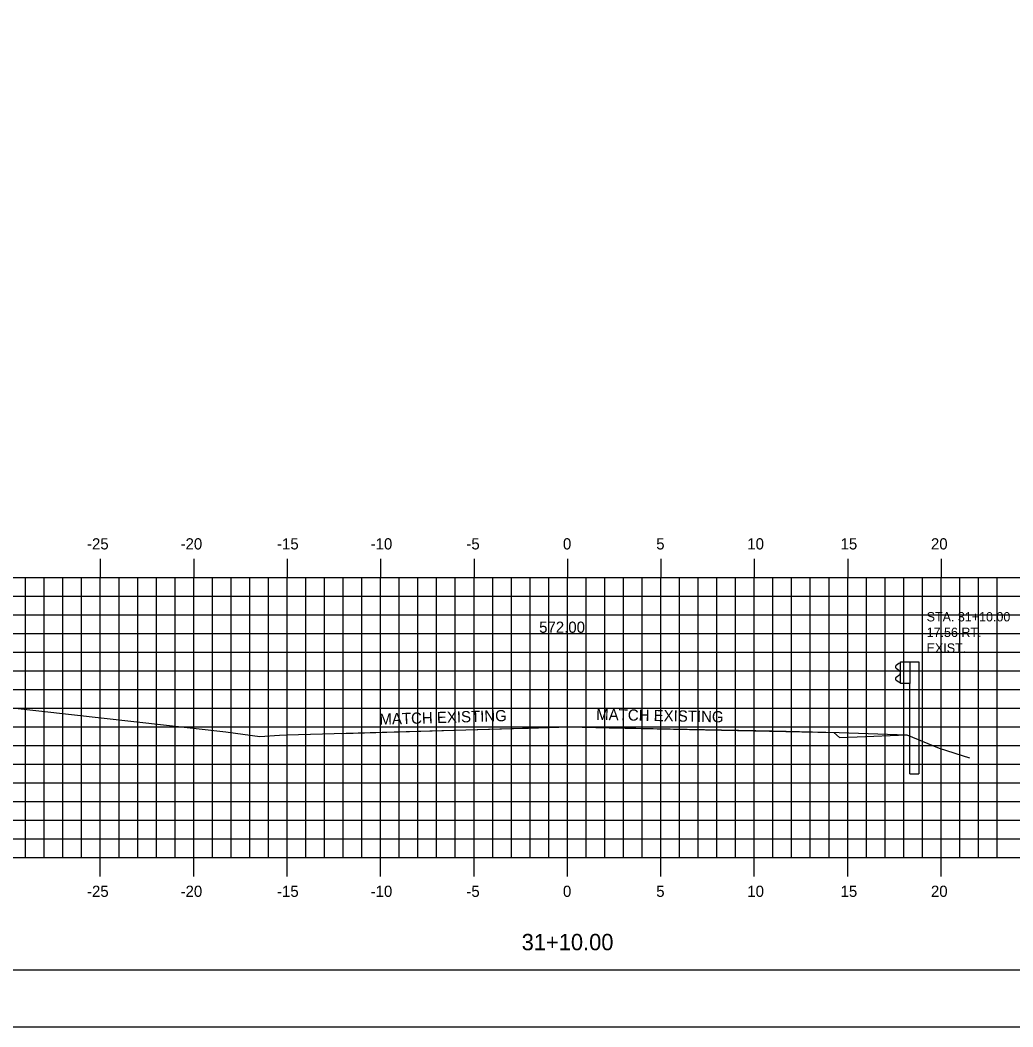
# Model space of a CAD drawing. Extents: x 1048552 to 1048722, y 781630 to 781740.
# Drawn here: x 1048606 to 1048659.1, y 781630.1 to 781684 of the extents above; entities that cross this region are included whole.
import ezdxf

# ---------------------------------------------------------------- set-up
doc = ezdxf.new("R2010")
doc.units = 0
for name, color, linetype in [('ANNOTATION', 7, 'Continuous'), ('D_Roadway_Centerline', 7, 'Continuous'), ('D_Roadway_Centerline_Text', 7, 'Continuous'), ('D_Text_Monospaced', 7, 'Continuous'), ('Default', 7, 'Continuous'), ('H_V ANNOTATION', 7, 'Continuous'), ('M_Guardrail', 7, 'Continuous'), ('MAJOR', 7, 'Continuous'), ('MINOR', 7, 'Continuous'), ('S_Guardrail_Beam', 7, 'Continuous'), ('S_Roadway_Centerline', 7, 'Continuous'), ('S_Roadway_Edge_Pavement', 7, 'Continuous')]:
    doc.layers.add(name, color=color, linetype=linetype)

msp = doc.modelspace()

# ---------------------------------------------------------------- linework, layer by layer
at = {"layer": 'D_Roadway_Centerline'}
msp.add_lwpolyline([(1048623.166, 781645.848), (1048635.246, 781646.2), (1048646.246, 781645.98), (1048649.796, 781645.893), (1048653.408, 781645.769)], dxfattribs=at)
at = {"layer": 'Default'}
msp.add_line((1048560.247, 781633.195), (1048720.247, 781633.195), dxfattribs=at)
msp.add_lwpolyline([(1048552.153, 781630.136), (1048722.153, 781630.136), (1048722.153, 781740.136), (1048552.153, 781740.136)], close=True, dxfattribs=at)
at = {"layer": 'M_Guardrail'}
for p, q in [((1048653.565, 781649.677), (1048654.057, 781649.677)), ((1048654.057, 781649.677), (1048654.057, 781643.677)), ((1048653.565, 781643.677), (1048653.565, 781648.511)), ((1048653.565, 781643.677), (1048654.057, 781643.677))]:
    msp.add_line(p, q, dxfattribs=at)
at = {"layer": 'MAJOR'}
for p, q in [((1048610.246, 781655.197), (1048610.246, 781654.195)), ((1048610.246, 781655.197), (1048610.246, 781654.195)), ((1048615.246, 781655.197), (1048615.246, 781654.195)), ((1048615.246, 781655.197), (1048615.246, 781654.195)), ((1048620.246, 781655.197), (1048620.246, 781654.195)), ((1048620.246, 781655.197), (1048620.246, 781654.195)), ((1048625.246, 781655.197), (1048625.246, 781654.195)), ((1048625.246, 781655.197), (1048625.246, 781654.195)), ((1048630.246, 781655.197), (1048630.246, 781654.195)), ((1048630.246, 781655.197), (1048630.246, 781654.195)), ((1048635.246, 781655.197), (1048635.246, 781654.195)), ((1048635.246, 781655.197), (1048635.246, 781654.195)), ((1048640.246, 781655.197), (1048640.246, 781654.195)), ((1048640.246, 781655.197), (1048640.246, 781654.195)), ((1048645.246, 781655.197), (1048645.246, 781654.195)), ((1048645.246, 781655.197), (1048645.246, 781654.195)), ((1048650.246, 781655.197), (1048650.246, 781654.195)), ((1048650.246, 781655.197), (1048650.246, 781654.195)), ((1048655.246, 781655.197), (1048655.246, 781654.195)), ((1048655.246, 781655.197), (1048655.246, 781654.195)), ((1048565.246, 781654.195), (1048705.246, 781654.195)), ((1048565.246, 781654.195), (1048705.246, 781654.195)), ((1048565.246, 781654.195), (1048705.246, 781654.195)), ((1048565.246, 781654.195), (1048705.246, 781654.195)), ((1048610.246, 781639.195), (1048610.246, 781654.195)), ((1048610.246, 781639.195), (1048610.246, 781654.195)), ((1048615.246, 781639.195), (1048615.246, 781654.195)), ((1048615.246, 781639.195), (1048615.246, 781654.195)), ((1048620.246, 781639.195), (1048620.246, 781654.195)), ((1048620.246, 781639.195), (1048620.246, 781654.195)), ((1048625.246, 781639.195), (1048625.246, 781654.195)), ((1048625.246, 781639.195), (1048625.246, 781654.195)), ((1048630.246, 781639.195), (1048630.246, 781654.195)), ((1048630.246, 781639.195), (1048630.246, 781654.195)), ((1048635.246, 781639.195), (1048635.246, 781654.195)), ((1048635.246, 781639.195), (1048635.246, 781654.195)), ((1048640.246, 781639.195), (1048640.246, 781654.195)), ((1048640.246, 781639.195), (1048640.246, 781654.195)), ((1048645.246, 781639.195), (1048645.246, 781654.195)), ((1048645.246, 781639.195), (1048645.246, 781654.195)), ((1048650.246, 781639.195), (1048650.246, 781654.195)), ((1048650.246, 781639.195), (1048650.246, 781654.195)), ((1048655.246, 781639.195), (1048655.246, 781654.195)), ((1048655.246, 781639.195), (1048655.246, 781654.195)), ((1048565.246, 781649.195), (1048705.246, 781649.195)), ((1048565.246, 781649.195), (1048705.246, 781649.195)), ((1048565.246, 781644.195), (1048705.246, 781644.195)), ((1048565.246, 781644.195), (1048705.246, 781644.195)), ((1048565.246, 781639.195), (1048705.246, 781639.195)), ((1048565.246, 781639.195), (1048705.246, 781639.195)), ((1048565.246, 781639.195), (1048705.246, 781639.195)), ((1048565.246, 781639.195), (1048705.246, 781639.195)), ((1048610.246, 781638.193), (1048610.246, 781639.195)), ((1048610.246, 781638.193), (1048610.246, 781639.195)), ((1048615.246, 781638.193), (1048615.246, 781639.195)), ((1048615.246, 781638.193), (1048615.246, 781639.195)), ((1048620.246, 781638.193), (1048620.246, 781639.195)), ((1048620.246, 781638.193), (1048620.246, 781639.195)), ((1048625.246, 781638.193), (1048625.246, 781639.195)), ((1048625.246, 781638.193), (1048625.246, 781639.195)), ((1048630.246, 781638.193), (1048630.246, 781639.195)), ((1048630.246, 781638.193), (1048630.246, 781639.195)), ((1048635.246, 781638.193), (1048635.246, 781639.195)), ((1048635.246, 781638.193), (1048635.246, 781639.195)), ((1048640.246, 781638.193), (1048640.246, 781639.195)), ((1048640.246, 781638.193), (1048640.246, 781639.195)), ((1048645.246, 781638.193), (1048645.246, 781639.195)), ((1048645.246, 781638.193), (1048645.246, 781639.195)), ((1048650.246, 781638.193), (1048650.246, 781639.195)), ((1048650.246, 781638.193), (1048650.246, 781639.195)), ((1048655.246, 781638.193), (1048655.246, 781639.195)), ((1048655.246, 781638.193), (1048655.246, 781639.195))]:
    msp.add_line(p, q, dxfattribs=at)
at = {"layer": 'MINOR'}
for p, q in [((1048606.246, 781639.195), (1048606.246, 781654.195)), ((1048606.246, 781639.195), (1048606.246, 781654.195)), ((1048607.246, 781639.195), (1048607.246, 781654.195)), ((1048607.246, 781639.195), (1048607.246, 781654.195)), ((1048608.246, 781639.195), (1048608.246, 781654.195)), ((1048608.246, 781639.195), (1048608.246, 781654.195)), ((1048609.246, 781639.195), (1048609.246, 781654.195)), ((1048609.246, 781639.195), (1048609.246, 781654.195)), ((1048611.246, 781639.195), (1048611.246, 781654.195)), ((1048611.246, 781639.195), (1048611.246, 781654.195)), ((1048612.246, 781639.195), (1048612.246, 781654.195)), ((1048612.246, 781639.195), (1048612.246, 781654.195)), ((1048613.246, 781639.195), (1048613.246, 781654.195)), ((1048613.246, 781639.195), (1048613.246, 781654.195)), ((1048614.246, 781639.195), (1048614.246, 781654.195)), ((1048614.246, 781639.195), (1048614.246, 781654.195)), ((1048616.246, 781639.195), (1048616.246, 781654.195)), ((1048616.246, 781639.195), (1048616.246, 781654.195)), ((1048617.246, 781639.195), (1048617.246, 781654.195)), ((1048617.246, 781639.195), (1048617.246, 781654.195)), ((1048618.246, 781639.195), (1048618.246, 781654.195)), ((1048618.246, 781639.195), (1048618.246, 781654.195)), ((1048619.246, 781639.195), (1048619.246, 781654.195)), ((1048619.246, 781639.195), (1048619.246, 781654.195)), ((1048621.246, 781639.195), (1048621.246, 781654.195)), ((1048621.246, 781639.195), (1048621.246, 781654.195)), ((1048622.246, 781639.195), (1048622.246, 781654.195)), ((1048622.246, 781639.195), (1048622.246, 781654.195)), ((1048623.246, 781639.195), (1048623.246, 781654.195)), ((1048623.246, 781639.195), (1048623.246, 781654.195)), ((1048624.246, 781639.195), (1048624.246, 781654.195)), ((1048624.246, 781639.195), (1048624.246, 781654.195)), ((1048626.246, 781639.195), (1048626.246, 781654.195)), ((1048626.246, 781639.195), (1048626.246, 781654.195)), ((1048627.246, 781639.195), (1048627.246, 781654.195)), ((1048627.246, 781639.195), (1048627.246, 781654.195)), ((1048628.246, 781639.195), (1048628.246, 781654.195)), ((1048628.246, 781639.195), (1048628.246, 781654.195)), ((1048629.246, 781639.195), (1048629.246, 781654.195)), ((1048629.246, 781639.195), (1048629.246, 781654.195)), ((1048631.246, 781639.195), (1048631.246, 781654.195)), ((1048631.246, 781639.195), (1048631.246, 781654.195)), ((1048632.246, 781639.195), (1048632.246, 781654.195)), ((1048632.246, 781639.195), (1048632.246, 781654.195)), ((1048633.246, 781639.195), (1048633.246, 781654.195)), ((1048633.246, 781639.195), (1048633.246, 781654.195)), ((1048634.246, 781639.195), (1048634.246, 781654.195)), ((1048634.246, 781639.195), (1048634.246, 781654.195)), ((1048636.246, 781639.195), (1048636.246, 781654.195)), ((1048636.246, 781639.195), (1048636.246, 781654.195)), ((1048637.246, 781639.195), (1048637.246, 781654.195)), ((1048637.246, 781639.195), (1048637.246, 781654.195)), ((1048638.246, 781639.195), (1048638.246, 781654.195)), ((1048638.246, 781639.195), (1048638.246, 781654.195)), ((1048639.246, 781639.195), (1048639.246, 781654.195)), ((1048639.246, 781639.195), (1048639.246, 781654.195)), ((1048641.246, 781639.195), (1048641.246, 781654.195)), ((1048641.246, 781639.195), (1048641.246, 781654.195)), ((1048642.246, 781639.195), (1048642.246, 781654.195)), ((1048642.246, 781639.195), (1048642.246, 781654.195)), ((1048643.246, 781639.195), (1048643.246, 781654.195)), ((1048643.246, 781639.195), (1048643.246, 781654.195)), ((1048644.246, 781639.195), (1048644.246, 781654.195)), ((1048644.246, 781639.195), (1048644.246, 781654.195)), ((1048646.246, 781639.195), (1048646.246, 781654.195)), ((1048646.246, 781639.195), (1048646.246, 781654.195)), ((1048647.246, 781639.195), (1048647.246, 781654.195)), ((1048647.246, 781639.195), (1048647.246, 781654.195)), ((1048648.246, 781639.195), (1048648.246, 781654.195)), ((1048648.246, 781639.195), (1048648.246, 781654.195)), ((1048649.246, 781639.195), (1048649.246, 781654.195)), ((1048649.246, 781639.195), (1048649.246, 781654.195)), ((1048651.246, 781639.195), (1048651.246, 781654.195)), ((1048651.246, 781639.195), (1048651.246, 781654.195)), ((1048652.246, 781639.195), (1048652.246, 781654.195)), ((1048652.246, 781639.195), (1048652.246, 781654.195)), ((1048653.246, 781639.195), (1048653.246, 781654.195)), ((1048653.246, 781639.195), (1048653.246, 781654.195)), ((1048654.246, 781639.195), (1048654.246, 781654.195)), ((1048654.246, 781639.195), (1048654.246, 781654.195)), ((1048656.246, 781639.195), (1048656.246, 781654.195)), ((1048656.246, 781639.195), (1048656.246, 781654.195)), ((1048657.246, 781639.195), (1048657.246, 781654.195)), ((1048657.246, 781639.195), (1048657.246, 781654.195)), ((1048658.246, 781639.195), (1048658.246, 781654.195)), ((1048658.246, 781639.195), (1048658.246, 781654.195)), ((1048565.246, 781653.195), (1048705.246, 781653.195)), ((1048565.246, 781653.195), (1048705.246, 781653.195)), ((1048565.246, 781652.195), (1048705.246, 781652.195)), ((1048565.246, 781652.195), (1048705.246, 781652.195)), ((1048565.246, 781651.195), (1048705.246, 781651.195)), ((1048565.246, 781651.195), (1048705.246, 781651.195)), ((1048565.246, 781650.195), (1048705.246, 781650.195)), ((1048565.246, 781650.195), (1048705.246, 781650.195)), ((1048565.246, 781648.195), (1048705.246, 781648.195)), ((1048565.246, 781648.195), (1048705.246, 781648.195)), ((1048565.246, 781647.195), (1048705.246, 781647.195)), ((1048565.246, 781647.195), (1048705.246, 781647.195)), ((1048565.246, 781646.195), (1048705.246, 781646.195)), ((1048565.246, 781646.195), (1048705.246, 781646.195)), ((1048565.246, 781645.195), (1048705.246, 781645.195)), ((1048565.246, 781645.195), (1048705.246, 781645.195)), ((1048565.246, 781643.195), (1048705.246, 781643.195)), ((1048565.246, 781643.195), (1048705.246, 781643.195)), ((1048565.246, 781642.195), (1048705.246, 781642.195)), ((1048565.246, 781642.195), (1048705.246, 781642.195)), ((1048565.246, 781641.195), (1048705.246, 781641.195)), ((1048565.246, 781641.195), (1048705.246, 781641.195)), ((1048565.246, 781640.195), (1048705.246, 781640.195)), ((1048565.246, 781640.195), (1048705.246, 781640.195))]:
    msp.add_line(p, q, dxfattribs=at)
at = {"layer": 'S_Guardrail_Beam'}
for p, q in [((1048653.076, 781649.677), (1048653.565, 781649.677)), ((1048653.076, 781648.511), (1048653.076, 781649.677)), ((1048653.565, 781649.677), (1048653.565, 781648.511)), ((1048652.977, 781649.583), (1048652.833, 781649.483)), ((1048652.833, 781649.34), (1048653.029, 781649.204)), ((1048653.076, 781649.605), (1048652.994, 781649.59)), ((1048653.062, 781649.14), (1048653.062, 781649.049)), ((1048653.029, 781648.984), (1048652.833, 781648.848)), ((1048652.833, 781648.705), (1048652.977, 781648.605)), ((1048652.994, 781648.598), (1048653.076, 781648.584)), ((1048653.565, 781648.511), (1048653.076, 781648.511))]:
    msp.add_line(p, q, dxfattribs=at)
for centre, major_axis, start_param, end_param in [((1048652.884, 781649.412), (-0.0877, 0), 5.323254, 7.243116), ((1048653.001, 781649.549), (-0.0417, 0), 4.886922, 5.323254), ((1048652.984, 781649.14), (0.0789, 0), 0, 0.959931), ((1048652.884, 781648.777), (-0.0877, 0), 5.323254, 7.243116), ((1048653.001, 781648.639), (-0.0417, 0), 0.959931, 1.396263), ((1048652.984, 781649.049), (0.0789, 0), 5.323254, 6.283185)]:
    msp.add_ellipse(centre, major_axis=major_axis, ratio=0.995501, start_param=start_param, end_param=end_param, dxfattribs=at)
at = {"layer": 'S_Roadway_Centerline'}
for points in [[(1048565.246, 781648.25), (1048579.277, 781648.059), (1048584.319, 781647.976), (1048600.326, 781647.557), (1048603.089, 781647.473), (1048603.286, 781647.461), (1048603.755, 781647.418), (1048616.956, 781645.932), (1048618.792, 781645.68), (1048619.828, 781645.755), (1048620.204, 781645.767), (1048632.993, 781646.121), (1048633.16, 781646.13), (1048635.318, 781646.203), (1048637.477, 781646.138), (1048649.509, 781645.9), (1048649.801, 781645.635), (1048650.76, 781645.672), (1048653.408, 781645.769), (1048655.135, 781645.053), (1048656.757, 781644.536)], [(1048635.318, 781646.203), (1048635.318, 781646.203)]]:
    msp.add_lwpolyline(points, dxfattribs=at)
at = {"layer": 'S_Roadway_Edge_Pavement'}
for points in [[(1048620.204, 781645.767), (1048620.204, 781645.767)], [(1048649.801, 781645.635), (1048649.801, 781645.635)]]:
    msp.add_lwpolyline(points, dxfattribs=at)

# ---------------------------------------------------------------- texts
at = {"layer": 'ANNOTATION'}
for rotation, p in [(1.6716, (1048625.192, 781646.307)), (358.8542, (1048636.78, 781646.57))]:
    msp.add_text('MATCH EXISTING', height=0.6, rotation=rotation, dxfattribs=at).set_placement(p)
at = {"layer": 'D_Roadway_Centerline_Text'}
msp.add_text('572.00', height=0.6, dxfattribs=at).set_placement((1048633.732, 781651.232))
at = {"layer": 'D_Text_Monospaced'}
for s, height, p in [('STA. 31+10.00', 0.49998, (1048654.471, 781651.842)), ('17.56 RT.', 0.5, (1048654.471, 781651.008)), ('EXIST. ', 0.5, (1048654.471, 781650.168))]:
    msp.add_text(s, height=height, dxfattribs=at).set_placement(p)
at = {"layer": 'H_V ANNOTATION'}
for s, height, p in [('-25', 0.6, (1048609.532, 781655.695)), ('-20', 0.6, (1048614.54, 781655.695)), ('-15', 0.6, (1048619.703, 781655.695)), ('-10', 0.6, (1048624.711, 781655.695)), ('-5', 0.6, (1048629.837, 781655.695)), ('0', 0.6, (1048635.006, 781655.695)), ('5', 0.6, (1048639.998, 781655.695)), ('10', 0.6, (1048644.872, 781655.695)), ('15', 0.6, (1048649.864, 781655.695)), ('20', 0.6, (1048654.7, 781655.695)), ('-25', 0.6, (1048609.532, 781637.095)), ('-20', 0.6, (1048614.54, 781637.095)), ('-15', 0.6, (1048619.703, 781637.095)), ('-10', 0.6, (1048624.711, 781637.095)), ('-5', 0.6, (1048629.837, 781637.095)), ('0', 0.6, (1048635.006, 781637.095)), ('5', 0.6, (1048639.998, 781637.095)), ('10', 0.6, (1048644.872, 781637.095)), ('15', 0.6, (1048649.864, 781637.095)), ('20', 0.6, (1048654.7, 781637.095)), ('31+10.00', 0.875, (1048632.797, 781634.238))]:
    msp.add_text(s, height=height, dxfattribs=at).set_placement(p)
at = {"layer": 'S_Roadway_Centerline'}
for s, p in [('C', (1048635.313, 781646.203)), ('L', (1048635.318, 781646.195))]:
    msp.add_text(s, height=0.0146, dxfattribs=at).set_placement(p)

doc.saveas('drawing.dxf')
